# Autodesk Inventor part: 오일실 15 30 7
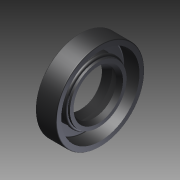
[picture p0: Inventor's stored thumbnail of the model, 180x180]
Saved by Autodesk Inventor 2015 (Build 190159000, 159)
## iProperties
Created: 2025-08
Part Number: 오일실 15 30 7
Material: 일반
Document SubType Name: Modeling
Designer: USER
Density: 1 g/cm^3
Appearance: 기본값
Author: USER
Author: jhkim
Description: 오일-실
Creation Date: 2025-08-05
Sending System: Autodesk Inventor 2026
Preprocessor: ST-DEVELOPER v20.1
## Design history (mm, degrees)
node "오일실 15 30 71"
body "Solid1"
node "기준1"
